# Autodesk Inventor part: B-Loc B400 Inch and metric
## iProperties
Shininess: 64.0
Length Units: 11272
Angle Units: 11279
Time Units: 11290
Mass Units: 11286
Length Display Precision: 3
Angle Display Precision: 2
Created: 2002-09
Part Number: B-Loc B400 Inch and metric
Material: Steel, Mild
Document SubType Name: Modeling
Designer: Mike Magill
Density: 0.0
Volumn: 0.0
Area: 0.0
PropertySet Name: Model Information
Control State: 0
Master: False
Checked Out: False
Author: Mike Magill
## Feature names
1. Revolution1
2. Extrusion2
3. Extrusion3
4. Chamfer1
5. Extrusion4
6. Circular Pattern2
7. Extrusion6
8. Circular Pattern3
